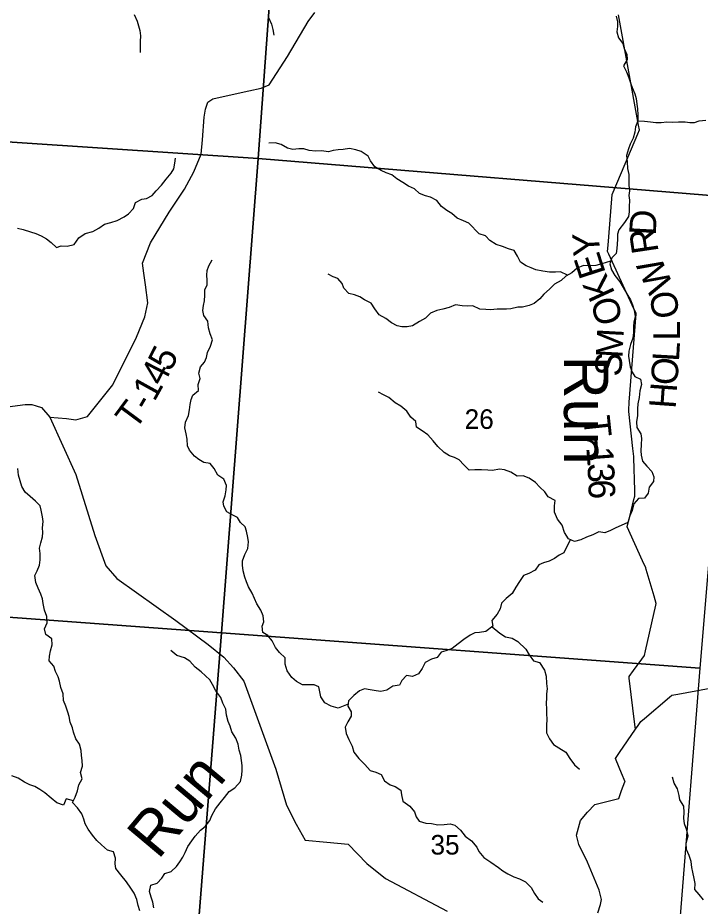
# Model space of a CAD drawing. Extents: x 1715311 to 2083412, y 146837 to 553079.
# Drawn here: x 1971823 to 1979519, y 348173 to 358196 of the extents above; entities that cross this region are included whole.
import ezdxf

# ---------------------------------------------------------------- set-up
doc = ezdxf.new("R2010")
doc.units = 0
for name, color, linetype in [('GM_X_County_Road', 7, 'Continuous'), ('GM_X_Minor_River', 7, 'Continuous'), ('GM_X_Minor_River_Text', 7, 'Continuous'), ('GM_X_Section', 7, 'Continuous'), ('GM_X_Section_Text', 7, 'Continuous'), ('GM_X_Township_Road', 7, 'Continuous'), ('GM_X_Township_Road_Text', 7, 'Continuous')]:
    doc.layers.add(name, color=color, linetype=linetype)

msp = doc.modelspace()

# ---------------------------------------------------------------- linework, layer by layer
at = {"layer": 'GM_X_County_Road'}
msp.add_lwpolyline([(1978366, 348098), (1978393, 348191), (1978405, 348249), (1978380, 348356), (1978248, 348669), (1978149, 348871), (1978125, 348975), (1978170, 349140), (1978248, 349234), (1978331, 349321), (1978588, 349386), (1978601, 349390), (1978633, 349477), (1978670, 349576), (1978671, 349577), (1978631, 349673), (1978571, 349820), (1978563, 349839), (1978610, 349909), (1978790, 350170), (1978820, 350213), (1978849, 350256), (1978890, 350291), (1979171, 350531), (1979199, 350555), (1979266, 350567), (1980097, 350720)], dxfattribs=at)
at = {"layer": 'GM_X_Minor_River'}
for points in [[(1973135, 358232), (1973171, 358156), (1973185, 358104), (1973201, 358054), (1973205, 357992), (1973203, 357928), (1973204, 357806)], [(1974649, 358199), (1974683, 358125), (1974701, 358065), (1974709, 357999)], [(1978573, 358213), (1978588, 358149), (1978586, 358097), (1978580, 358039), (1978598, 357971)], [(1978598, 357971), (1978646, 357905), (1978662, 357851), (1978692, 357781), (1978694, 357725), (1978654, 357655), (1978688, 357587), (1978715, 357520), (1978733, 357462), (1978751, 357408), (1978781, 357338), (1978795, 357284), (1978805, 357222), (1978811, 357170), (1978817, 357102), (1978815, 357034), (1978789, 356964), (1978780, 356904), (1978762, 356838), (1978730, 356769), (1978712, 356717), (1978688, 356643), (1978694, 356571), (1978700, 356497), (1978713, 356427), (1978715, 356377), (1978713, 356307), (1978723, 356243), (1978715, 356192), (1978721, 356140), (1978719, 356064), (1978717, 356006), (1978712, 355954), (1978664, 355886), (1978600, 355804), (1978588, 355754), (1978586, 355699), (1978582, 355643), (1978578, 355593), (1978572, 355537), (1978521, 355489), (1978499, 355421), (1978517, 355353), (1978555, 355287), (1978611, 355217), (1978649, 355153), (1978693, 355083), (1978733, 355013), (1978757, 354959), (1978773, 354899), (1978786, 354827), (1978770, 354766), (1978766, 354712), (1978768, 354644), (1978760, 354582), (1978734, 354510), (1978714, 354434), (1978710, 354380), (1978719, 354330), (1978731, 354260), (1978753, 354198), (1978781, 354148), (1978845, 354118), (1978857, 354058), (1978839, 353987), (1978829, 353913), (1978817, 353839), (1978811, 353783), (1978812, 353709), (1978802, 353637), (1978806, 353575), (1978850, 353503), (1978858, 353449), (1978852, 353381), (1978848, 353312), (1978854, 353260), (1978868, 353194), (1978919, 353138), (1978975, 353078), (1978995, 353016), (1978991, 352966), (1978943, 352902), (1978933, 352832), (1978889, 352776), (1978823, 352772), (1978772, 352711), (1978752, 352639), (1978726, 352577), (1978704, 352503), (1978628, 352467), (1978568, 352441), (1978508, 352410), (1978443, 352386), (1978377, 352396), (1978307, 352364), (1978237, 352336), (1978171, 352308), (1978103, 352289), (1978035, 352317), (1977989, 352391), (1977963, 352471)], [(1978815, 357034), (1978891, 357030), (1978959, 357022), (1979017, 357014), (1979077, 357014), (1979143, 357021), (1979209, 357019), (1979275, 357021), (1979349, 357021), (1979401, 357015), (1979454, 357015), (1979508, 357035), (1979582, 357042)], [(1978023, 355291), (1977942, 355330), (1977888, 355326), (1977818, 355325), (1977744, 355337), (1977666, 355353), (1977614, 355375), (1977558, 355397), (1977494, 355439), (1977458, 355505), (1977420, 355569), (1977358, 355589), (1977288, 355617), (1977218, 355639), (1977148, 355685), (1977098, 355735), (1977028, 355760), (1976910, 355878), (1976850, 355904), (1976780, 355934), (1976718, 355988), (1976662, 356022), (1976600, 356066), (1976548, 356134), (1976476, 356174), (1976422, 356188), (1976352, 356214), (1976296, 356268), (1976228, 356298), (1976164, 356336), (1976098, 356379), (1976042, 356425), (1975976, 356447), (1975922, 356473), (1975850, 356515), (1975802, 356583), (1975776, 356633), (1975696, 356689), (1975636, 356705), (1975564, 356721), (1975493, 356711), (1975435, 356707), (1975381, 356698), (1975327, 356682), (1975249, 356694), (1975179, 356690), (1975109, 356698), (1975049, 356716), (1974993, 356716), (1974923, 356710), (1974863, 356726), (1974795, 356765), (1974724, 356785), (1974656, 356781)], [(1971819, 355822), (1971883, 355806), (1971965, 355782), (1972027, 355762), (1972085, 355736), (1972145, 355702), (1972199, 355661), (1972259, 355605), (1972311, 355625), (1972379, 355621), (1972459, 355639), (1972511, 355715), (1972582, 355761), (1972670, 355786), (1972738, 355822), (1972800, 355868), (1972874, 355886), (1972942, 355910), (1973021, 355951), (1973073, 355983), (1973129, 356043), (1973149, 356113), (1973221, 356149), (1973273, 356159), (1973339, 356190), (1973382, 356242), (1973442, 356308), (1973498, 356374), (1973552, 356442), (1973582, 356493), (1973594, 356557), (1973603, 356611)], [(1975549, 350454), (1975437, 350407), (1975359, 350429), (1975287, 350469), (1975241, 350537), (1975230, 350593), (1975218, 350647), (1975164, 350671), (1975035, 350671), (1974965, 350709), (1974915, 350753), (1974861, 350827), (1974840, 350905), (1974838, 350975), (1974774, 351035), (1974728, 351093), (1974690, 351169), (1974642, 351229), (1974588, 351263), (1974580, 351331), (1974598, 351383), (1974590, 351449), (1974564, 351513), (1974520, 351585), (1974494, 351643), (1974465, 351705), (1974425, 351777), (1974401, 351833), (1974383, 351885), (1974365, 351957), (1974357, 352019), (1974357, 352071), (1974383, 352140), (1974417, 352208), (1974424, 352284), (1974416, 352334), (1974404, 352404), (1974388, 352454), (1974336, 352504), (1974300, 352558), (1974248, 352584), (1974180, 352624), (1974146, 352686), (1974140, 352736), (1974162, 352804), (1974174, 352870), (1974176, 352920), (1974147, 352992), (1974079, 353036), (1974039, 353110), (1973991, 353166), (1973921, 353178), (1973865, 353212), (1973815, 353252), (1973759, 353318), (1973737, 353368), (1973733, 353444), (1973721, 353502), (1973707, 353570), (1973715, 353633), (1973747, 353711), (1973761, 353773), (1973768, 353833), (1973780, 353889), (1973798, 353939), (1973860, 353993), (1973856, 354059), (1973878, 354126), (1973864, 354186), (1973885, 354260), (1973929, 354312), (1973953, 354362), (1973963, 354420), (1973997, 354492), (1974019, 354561), (1973993, 354629), (1973972, 354699), (1973966, 354773), (1973920, 354839), (1973910, 354895), (1973916, 354949), (1973930, 355003), (1973932, 355067), (1973932, 355127), (1973958, 355185), (1973958, 355235), (1973955, 355292), (1973959, 355344), (1973977, 355396), (1974015, 355464)], [(1978509, 355452), (1978409, 355421), (1978343, 355401), (1978271, 355396), (1978203, 355400), (1978133, 355372), (1978070, 355318), (1978004, 355280), (1977950, 355233), (1977874, 355189), (1977820, 355133), (1977757, 355077), (1977709, 355025), (1977645, 354974), (1977589, 354952), (1977515, 354930), (1977463, 354930), (1977385, 354912), (1977333, 354908), (1977228, 354908), (1977154, 354903), (1977100, 354905), (1977032, 354907), (1976954, 354945), (1976900, 354941), (1976834, 354947), (1976758, 354959), (1976688, 354928), (1976616, 354910), (1976547, 354894), (1976477, 354864), (1976421, 354808), (1976355, 354770), (1976273, 354721), (1976213, 354711), (1976153, 354711), (1976101, 354721), (1976038, 354753), (1975975, 354805), (1975898, 354845), (1975851, 354913), (1975809, 354977), (1975733, 355015), (1975679, 355047), (1975621, 355071), (1975558, 355086), (1975500, 355144), (1975483, 355200), (1975431, 355256), (1975379, 355274), (1975323, 355304)], [(1977963, 352471), (1977911, 352541), (1977877, 352617), (1977875, 352692), (1977883, 352750), (1977805, 352790), (1977765, 352848), (1977711, 352900), (1977661, 352955), (1977591, 353003), (1977521, 353027), (1977453, 353023), (1977383, 353071), (1977313, 353097), (1977257, 353103), (1977175, 353087), (1977123, 353093), (1977051, 353098), (1976979, 353098), (1976915, 353092), (1976855, 353154), (1976799, 353208), (1976747, 353236), (1976693, 353254), (1976633, 353292), (1976561, 353360), (1976507, 353424), (1976449, 353492), (1976383, 353538), (1976321, 353576), (1976311, 353640), (1976257, 353690), (1976209, 353758), (1976141, 353816), (1976079, 353852), (1976009, 353914), (1975949, 353941), (1975891, 353973)], [(1972068, 352021), (1972076, 352081), (1972076, 352153), (1972066, 352211), (1972084, 352273), (1972100, 352341), (1972105, 352391), (1972103, 352441), (1972109, 352514), (1972103, 352566), (1972087, 352640), (1972075, 352690), (1972023, 352742), (1971961, 352796), (1971905, 352844), (1971867, 352908), (1971851, 352972), (1971831, 353036), (1971824, 353110)], [(1978055, 352309), (1978010, 352225), (1977980, 352161), (1977928, 352135), (1977874, 352097), (1977814, 352066), (1977752, 352046), (1977698, 352024), (1977657, 351964), (1977587, 351926), (1977527, 351906), (1977483, 351837), (1977439, 351771), (1977399, 351701), (1977332, 351643), (1977280, 351593), (1977264, 351529), (1977230, 351468), (1977170, 351398), (1977180, 351332), (1977103, 351272), (1977031, 351262), (1976979, 351256), (1976923, 351231), (1976855, 351181), (1976791, 351135), (1976721, 351079), (1976650, 351055), (1976598, 351038), (1976554, 350980), (1976490, 350960), (1976416, 350922), (1976384, 350856), (1976343, 350794), (1976275, 350765), (1976207, 350775), (1976155, 350721), (1976127, 350667), (1976053, 350655), (1975985, 350611), (1975918, 350596), (1975864, 350602), (1975798, 350616), (1975732, 350626), (1975678, 350604), (1975612, 350550), (1975554, 350492), (1975546, 350429), (1975584, 350367), (1975581, 350317), (1975545, 350253), (1975515, 350195), (1975525, 350123), (1975555, 350053), (1975593, 349979), (1975611, 349911), (1975669, 349839), (1975735, 349771), (1975797, 349703), (1975859, 349685), (1975921, 349661), (1975959, 349589), (1976023, 349543), (1976079, 349525), (1976141, 349483), (1976149, 349431), (1976167, 349359), (1976243, 349303), (1976298, 349239), (1976316, 349181), (1976348, 349131), (1976424, 349111), (1976488, 349105), (1976561, 349090), (1976631, 349096), (1976699, 349102), (1976751, 349088), (1976817, 349032), (1976869, 348964), (1976939, 348910), (1976999, 348840), (1977023, 348790), (1977079, 348724), (1977159, 348672), (1977243, 348610), (1977295, 348574), (1977351, 348538), (1977417, 348503), (1977481, 348481), (1977547, 348447), (1977613, 348385), (1977651, 348317), (1977693, 348257), (1977745, 348219)], [(1973198, 348121), (1973182, 348181), (1973166, 348251), (1973136, 348320), (1973098, 348378), (1973050, 348450), (1972984, 348526), (1972927, 348598), (1972921, 348650), (1972925, 348716), (1972903, 348786), (1972833, 348806), (1972767, 348866), (1972715, 348916), (1972665, 348976), (1972617, 349042), (1972583, 349104), (1972567, 349156), (1972545, 349216), (1972495, 349282), (1972441, 349344), (1972471, 349404), (1972496, 349476), (1972512, 349544), (1972548, 349610), (1972530, 349680), (1972552, 349752), (1972550, 349818), (1972540, 349873), (1972539, 349931), (1972519, 350003), (1972477, 350063), (1972451, 350137), (1972441, 350187), (1972413, 350249), (1972403, 350313), (1972387, 350363), (1972363, 350431), (1972339, 350495), (1972333, 350571), (1972310, 350639), (1972294, 350711), (1972280, 350761), (1972250, 350821), (1972228, 350883), (1972178, 350943), (1972180, 350995), (1972192, 351054), (1972212, 351122), (1972206, 351188), (1972140, 351240), (1972123, 351304), (1972153, 351370), (1972149, 351440), (1972125, 351512), (1972111, 351588), (1972101, 351642), (1972083, 351694), (1972053, 351762), (1972027, 351826), (1972017, 351904), (1972040, 351955), (1972068, 352021)], [(1977172, 351326), (1977258, 351254), (1977322, 351212), (1977398, 351196), (1977464, 351158), (1977554, 351074), (1977590, 351010), (1977640, 350942), (1977708, 350921), (1977762, 350835), (1977781, 350769), (1977787, 350684), (1977793, 350624), (1977787, 350570), (1977785, 350520), (1977783, 350464), (1977785, 350398), (1977787, 350342), (1977791, 350282), (1977786, 350212), (1977786, 350130), (1977818, 350060), (1977866, 349996), (1977924, 349960), (1978002, 349912), (1978050, 349840), (1978100, 349770), (1978158, 349720)], [(1973356, 348154), (1973346, 348220), (1973328, 348274), (1973309, 348340), (1973323, 348410), (1973393, 348434), (1973447, 348488), (1973481, 348541), (1973551, 348565), (1973614, 348623), (1973652, 348673), (1973686, 348725), (1973712, 348781), (1973740, 348846), (1973786, 348910), (1973822, 348962), (1973885, 349032), (1973937, 349072), (1973989, 349142), (1974013, 349195), (1974053, 349273), (1974104, 349341), (1974156, 349401), (1974206, 349469), (1974272, 349510), (1974334, 349580), (1974351, 349652), (1974355, 349708), (1974353, 349760), (1974347, 349816), (1974337, 349872), (1974321, 349934), (1974307, 350000), (1974283, 350070), (1974237, 350140), (1974219, 350204), (1974197, 350256), (1974178, 350329), (1974168, 350397), (1974134, 350465), (1974114, 350529), (1974056, 350605), (1974020, 350675), (1973990, 350727), (1973940, 350771), (1973890, 350817), (1973824, 350869), (1973762, 350937), (1973702, 350977), (1973616, 351002), (1973548, 351058)], [(1972451, 349364), (1972369, 349385), (1972337, 349313), (1972265, 349339), (1972199, 349393), (1972127, 349453), (1972073, 349489), (1972015, 349523), (1971957, 349541), (1971899, 349571), (1971827, 349619), (1971757, 349643)], [(1979555, 348245), (1979509, 348307), (1979457, 348361), (1979461, 348431), (1979451, 348487), (1979436, 348559), (1979426, 348611), (1979418, 348677), (1979396, 348747), (1979366, 348813), (1979362, 348885), (1979382, 348967), (1979370, 349031), (1979342, 349103), (1979333, 349167), (1979339, 349232), (1979333, 349302), (1979291, 349372), (1979281, 349422), (1979263, 349496), (1979225, 349560), (1979205, 349630)]]:
    msp.add_lwpolyline(points, dxfattribs=at)
at = {"layer": 'GM_X_Section'}
for points in [[(1969556, 362398), (1974920, 361942), (1974535, 356607), (1969150, 356965)], [(1974920, 361942), (1980359, 361470), (1979957, 356163), (1974535, 356607)], [(1969150, 356965), (1974535, 356607), (1974119, 351259), (1968750, 351654)], [(1974535, 356607), (1979957, 356163), (1979516, 350859), (1974119, 351259)], [(1968750, 351654), (1974119, 351259), (1973697, 345890), (1973161, 345930), (1968371, 346279)], [(1974119, 351259), (1979516, 350859), (1979086, 345460), (1978816, 345484), (1973697, 345890)]]:
    msp.add_lwpolyline(points, close=True, dxfattribs=at)
at = {"layer": 'GM_X_Township_Road'}
for points in [[(1972186, 353689), (1972374, 353677), (1972476, 353662), (1972610, 353698), (1972893, 354056), (1973163, 354594), (1973255, 354821), (1973290, 354979), (1973263, 355185), (1973243, 355314), (1973230, 355428), (1973320, 355656), (1973532, 356004), (1973702, 356262), (1973809, 356457), (1973890, 356659), (1973906, 356819), (1973925, 357074), (1973941, 357166), (1973966, 357244), (1974024, 357282), (1974240, 357331), (1974430, 357371), (1974566, 357402), (1974658, 357440), (1974863, 357758), (1975097, 358155), (1975173, 358254)], [(1978790, 350170), (1978783, 350222), (1978719, 350745), (1978717, 350763), (1978767, 350833), (1978860, 350961), (1978889, 351002), (1978901, 351056), (1979019, 351569), (1979023, 351587), (1978999, 351670), (1978910, 351973), (1978905, 351992), (1978869, 352070), (1978696, 352454), (1978695, 352457), (1978720, 352556), (1978772, 352760), (1978783, 352800), (1978781, 352864), (1978771, 353232), (1978771, 353247), (1978761, 353337), (1978714, 353755), (1978713, 353770), (1978719, 353860), (1978795, 354857), (1978795, 354860), (1978752, 354953), (1978489, 355528), (1978474, 355560), (1978480, 355629), (1978524, 356154), (1978528, 356203), (1978550, 356255), (1978815, 356886), (1978835, 356933), (1978825, 356986), (1978599, 358229)], [(1971708, 353806), (1971908, 353833), (1971980, 353832), (1972030, 353818), (1972090, 353800), (1972186, 353689), (1972479, 353043), (1972691, 352355), (1972816, 352013), (1972941, 351869), (1973606, 351398), (1973969, 351126), (1974146, 350983), (1974256, 350864), (1974371, 350712), (1974732, 349720), (1974854, 349315), (1974962, 349100), (1975063, 348919), (1975307, 348895), (1975549, 348872), (1975758, 348655), (1975971, 348486), (1976666, 348119)]]:
    msp.add_lwpolyline(points, dxfattribs=at)

# ---------------------------------------------------------------- texts
at = {"layer": 'GM_X_Minor_River_Text'}
for height, rotation, p in [(500.1, 270.0004, (1977983, 354383)), (500, 50.0017, (1973404, 348689))]:
    msp.add_text('Run', height=height, rotation=rotation, dxfattribs=at).set_placement(p)
at = {"layer": 'GM_X_Section_Text'}
for s, p in [('26', (1976862, 353558)), ('35', (1976477, 348756))]:
    msp.add_text(s, height=221, rotation=0, dxfattribs=at).set_placement(p)
at = {"layer": 'GM_X_Township_Road_Text'}
for s, rotation, p in [('D', 86.8718, (1979017, 355735)), ('R', 98.4767, (1979051, 355557)), ('Y', 93.3168, (1978391, 355512)), ('E', 107.985, (1978456, 355318)), ('W', 114.6662, (1979223, 355176)), ('K', 114.8526, (1978564, 355087)), ('O', 104.1373, (1978649, 354774)), ('O', 98.5452, (1979288, 354827)), ('L', 90.084, (1979292, 354555)), ('M', 86.9496, (1978641, 354351)), ('L', 86.7655, (1979279, 354312)), ('5', 63.2242, (1973544, 354193)), ('4', 62.7762, (1973458, 354027)), ('S', 85.8101, (1978626, 354143)), ('O', 85.9257, (1979260, 354044)), ('1', 61.0671, (1973364, 353856)), ('H', 85.8801, (1979241, 353780)), ('-', 59.41, (1973297, 353742)), ('T', 53.4335, (1973144, 353533)), ('T', 275.9422, (1978199, 353693)), ('-', 275.4333, (1978222, 353470)), ('1', 274.2606, (1978234, 353349)), ('3', 272.8268, (1978247, 353167)), ('6', 271.806, (1978256, 352984))]:
    msp.add_text(s, height=300, rotation=rotation, dxfattribs=at).set_placement(p)

doc.saveas('drawing.dxf')
